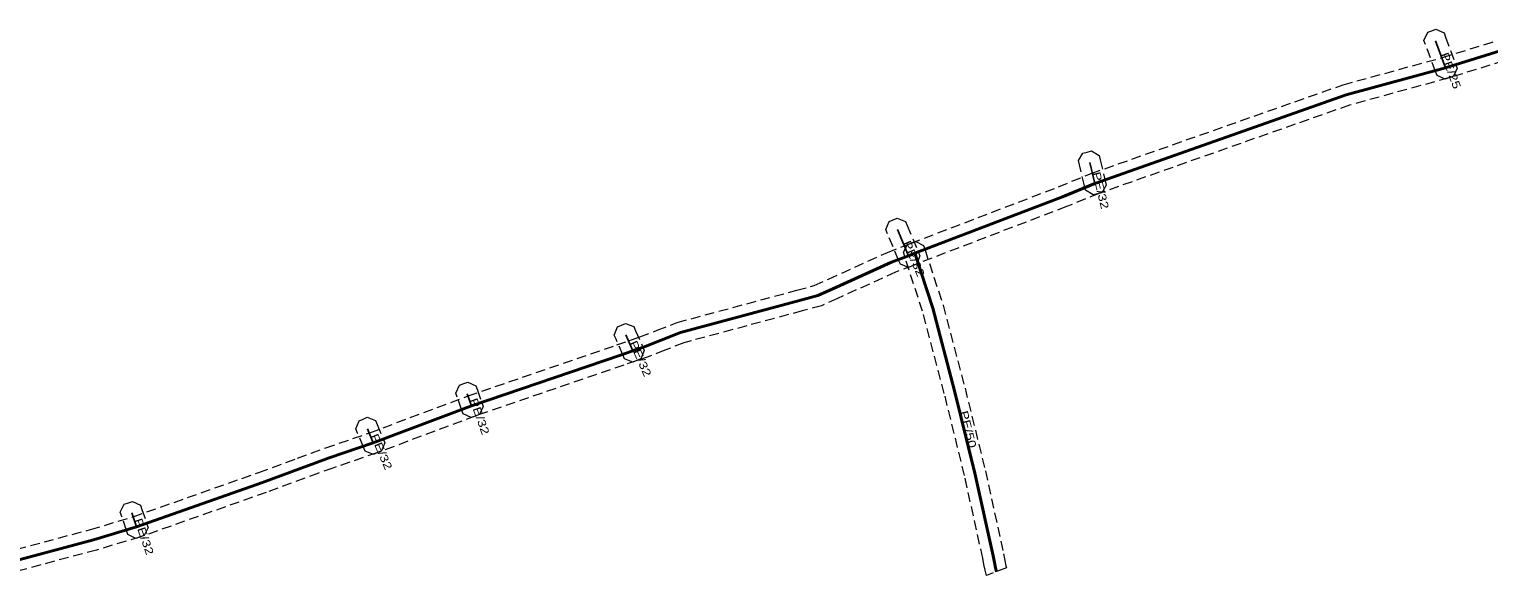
# Model space of a CAD drawing. Extents: x -772780 to -772236, y -1033108 to -1032817.
# Drawn here: x -772643 to -772506.2, y -1033031.8 to -1032979.8 of the extents above; entities that cross this region are included whole.
import ezdxf

# ---------------------------------------------------------------- set-up
doc = ezdxf.new("R2010")
doc.units = 0
doc.header["$LTSCALE"] = 0.3
doc.linetypes.add('MEDIUM_DASHED', pattern=[4.5, 3, -1.5])
doc.layers.add('1', color=7, linetype='MEDIUM_DASHED', lineweight=13)
doc.layers.add('24', color=7, linetype='Continuous', lineweight=25)
doc.layers.add('30', color=7, linetype='Continuous')

msp = doc.modelspace()

# ---------------------------------------------------------------- linework, layer by layer
at = {"layer": '1'}
for points in [[(-772511.048, -1032984.16), (-772511.192, -1032983.771), (-772512.13, -1032981.246), (-772512.275, -1032980.858), (-772511.93, -1032980.105), (-772511.541, -1032979.961), (-772511.153, -1032979.816), (-772510.4, -1032980.161), (-772510.256, -1032980.55), (-772509.318, -1032983.075), (-772509.173, -1032983.463), (-772509.518, -1032984.216), (-772509.907, -1032984.36), (-772510.295, -1032984.505)], [(-772543.984, -1032994.899), (-772544.082, -1032994.497), (-772544.562, -1032992.527), (-772544.66, -1032992.124), (-772544.229, -1032991.416), (-772543.827, -1032991.318), (-772543.424, -1032991.22), (-772542.716, -1032991.651), (-772542.618, -1032992.053), (-772542.138, -1032994.023), (-772542.04, -1032994.426), (-772542.471, -1032995.134), (-772542.873, -1032995.232), (-772543.276, -1032995.33)], [(-772561.34, -1033001.81), (-772561.501, -1033001.429), (-772562.541, -1032998.969), (-772562.702, -1032998.588), (-772562.39, -1032997.82), (-772562.009, -1032997.659), (-772561.628, -1032997.498), (-772560.86, -1032997.81), (-772560.699, -1032998.191), (-772559.659, -1033000.651), (-772559.498, -1033001.032), (-772559.81, -1033001.8), (-772560.191, -1033001.961), (-772560.572, -1033002.122)], [(-772551.392, -1033030.262), (-772553.277, -1033030.97), (-772553.397, -1033030.484), (-772553.502, -1033029.941), (-772553.619, -1033029.344), (-772555.324, -1033021.617), (-772557.219, -1033013.928), (-772559.259, -1033006.233), (-772560.931, -1033001.1), (-772561.059, -1033000.706), (-772560.684, -1032999.967), (-772560.29, -1032999.839), (-772559.896, -1032999.711), (-772559.157, -1033000.086), (-772559.029, -1033000.48), (-772557.341, -1033005.667), (-772555.281, -1033013.432), (-772553.376, -1033021.163), (-772551.661, -1033028.936), (-772551.538, -1033029.559), (-772551.443, -1033030.056)], [(-772587.172, -1033010.699), (-772587.337, -1033010.319), (-772587.977, -1033008.849), (-772588.142, -1033008.469), (-772587.839, -1033007.698), (-772587.459, -1033007.533), (-772587.079, -1033007.368), (-772586.308, -1033007.671), (-772586.143, -1033008.051), (-772585.503, -1033009.521), (-772585.338, -1033009.901), (-772585.641, -1033010.672), (-772586.021, -1033010.837), (-772586.401, -1033011.002)], [(-772602.312, -1033015.822), (-772602.45, -1033015.432), (-772602.857, -1033014.286), (-772602.996, -1033013.895), (-772602.64, -1033013.147), (-772602.25, -1033013.009), (-772601.859, -1033012.87), (-772601.111, -1033013.226), (-772600.973, -1033013.616), (-772600.566, -1033014.762), (-772600.427, -1033015.153), (-772600.783, -1033015.901), (-772601.173, -1033016.039), (-772601.564, -1033016.178)], [(-772611.477, -1033019.324), (-772611.64, -1033018.943), (-772612.2, -1033017.633), (-772612.363, -1033017.252), (-772612.054, -1033016.483), (-772611.673, -1033016.32), (-772611.292, -1033016.157), (-772610.523, -1033016.466), (-772610.36, -1033016.847), (-772609.8, -1033018.157), (-772609.637, -1033018.538), (-772609.946, -1033019.307), (-772610.327, -1033019.47), (-772610.708, -1033019.633)], [(-772633.716, -1033027.137), (-772633.85, -1033026.745), (-772634.296, -1033025.439), (-772634.43, -1033025.047), (-772634.065, -1033024.304), (-772633.673, -1033024.17), (-772633.281, -1033024.036), (-772632.538, -1033024.401), (-772632.404, -1033024.793), (-772631.958, -1033026.099), (-772631.824, -1033026.491), (-772632.189, -1033027.234), (-772632.581, -1033027.368), (-772632.973, -1033027.502)]]:
    msp.add_lwpolyline(points, close=True, dxfattribs=at)
for points in [[(-772649.366, -1033029.916), (-772637.216, -1033026.666), (-772633.214, -1033025.471), (-772621.438, -1033021.314), (-772617.832, -1033019.993), (-772616.557, -1033019.519), (-772615.183, -1033019.023), (-772611.058, -1033017.609), (-772601.845, -1033014.156), (-772587.903, -1033009.383), (-772586.746, -1033008.975), (-772586.518, -1033008.898), (-772585.738, -1033008.636), (-772584.125, -1033008.011), (-772582.246, -1033007.274), (-772571.045, -1033004.266), (-772569.404, -1033003.82), (-772568.064, -1033003.218), (-772562.549, -1033000.717), (-772560.95, -1033000.111), (-772560.351, -1032999.861), (-772546.511, -1032994.573), (-772543.466, -1032993.325), (-772519.855, -1032985.02), (-772510.535, -1032982.463), (-772505.481, -1032980.902)], [(-772504.807, -1032982.786), (-772509.975, -1032984.383), (-772519.257, -1032986.93), (-772542.754, -1032995.195), (-772545.775, -1032996.433), (-772559.609, -1033001.719), (-772560.21, -1033001.969), (-772561.781, -1033002.565), (-772567.242, -1033005.042), (-772568.728, -1033005.708), (-772570.523, -1033006.196), (-772581.62, -1033009.176), (-772583.399, -1033009.875), (-772585.058, -1033010.518), (-772585.882, -1033010.794), (-772586.094, -1033010.865), (-772587.247, -1033011.273), (-772601.171, -1033016.038), (-772610.382, -1033019.491), (-772614.519, -1033020.909), (-772615.869, -1033021.397), (-772617.14, -1033021.869), (-772620.762, -1033023.196), (-772632.594, -1033027.373), (-772636.672, -1033028.59), (-772648.834, -1033031.844)]]:
    msp.add_lwpolyline(points, dxfattribs=at)
at = {"layer": '24'}
for p, q in [((-772510.255, -1032983.423), (-772511.193, -1032980.898)), ((-772543.11, -1032994.26), (-772543.59, -1032992.29)), ((-772560.58, -1033001.04), (-772561.62, -1032998.58)), ((-772586.42, -1033009.92), (-772587.06, -1033008.45)), ((-772601.508, -1033015.097), (-772601.915, -1033013.951)), ((-772610.72, -1033018.55), (-772611.28, -1033017.24)), ((-772632.904, -1033026.422), (-772633.35, -1033025.116))]:
    msp.add_line(p, q, dxfattribs=at)
at = {"layer": '24', "lineweight": 40}
for points in [[(-772505.144, -1032981.844), (-772510.255, -1032983.423), (-772519.556, -1032985.975), (-772543.11, -1032994.26), (-772546.143, -1032995.503), (-772559.98, -1033000.79), (-772560.58, -1033001.04), (-772562.165, -1033001.641), (-772567.653, -1033004.13), (-772569.066, -1033004.764), (-772570.784, -1033005.231), (-772581.933, -1033008.225), (-772583.762, -1033008.943), (-772585.398, -1033009.577), (-772586.2, -1033009.846), (-772586.42, -1033009.92), (-772587.575, -1033010.328), (-772601.508, -1033015.097), (-772610.72, -1033018.55), (-772614.851, -1033019.966), (-772616.213, -1033020.458), (-772617.486, -1033020.931), (-772621.1, -1033022.255), (-772632.904, -1033026.422), (-772636.944, -1033027.628), (-772649.1, -1033030.88)], [(-772559.98, -1033000.79), (-772558.3, -1033005.95), (-772556.25, -1033013.68), (-772554.35, -1033021.39), (-772552.64, -1033029.14), (-772552.519, -1033029.749), (-772552.42, -1033030.27), (-772552.335, -1033030.616)]]:
    msp.add_lwpolyline(points, dxfattribs=at)

# ---------------------------------------------------------------- texts
at = {"layer": '30', "width": 1.3}
for s, rotation, p in [('PE/25', 290.379, (-772510.724, -1032982.16)), ('PE/32', 283.694, (-772543.35, -1032993.275)), ('PE/32', 292.917, (-772561.1, -1032999.81)), ('PE/32', 293.527, (-772586.74, -1033009.185)), ('PE/32', 289.552, (-772601.711, -1033014.524)), ('PE/50', 283.844, (-772555.764, -1033015.651)), ('PE/32', 293.146, (-772611, -1033017.895)), ('PE/32', 288.855, (-772633.127, -1033025.769))]:
    msp.add_text(s, height=0.75, rotation=rotation, dxfattribs=at).set_placement(p)

doc.saveas('drawing.dxf')
